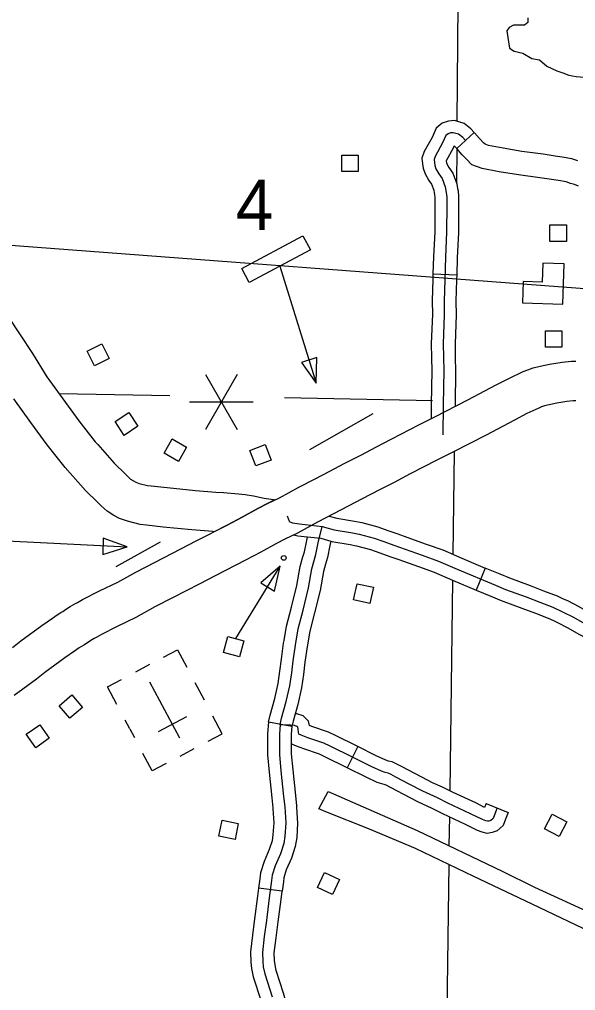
# Model space of a CAD drawing. Extents: x 61396 to 64680, y 55472 to 57605.
# Drawn here: x 62199.2 to 62308.8, y 55932.3 to 56123.6 of the extents above; entities that cross this region are included whole.
import ezdxf

# ---------------------------------------------------------------- set-up
doc = ezdxf.new("R2010")
doc.units = 0
for name, color, linetype in [('10', 7, 'Continuous'), ('15', 7, 'Continuous'), ('31', 7, 'Continuous'), ('35', 7, 'Continuous'), ('45', 7, 'Continuous'), ('46', 7, 'Continuous'), ('48', 7, 'Continuous'), ('5', 7, 'Continuous'), ('56', 7, 'Continuous'), ('57', 7, 'Continuous'), ('58', 7, 'Continuous'), ('Default', 7, 'Continuous')]:
    doc.layers.add(name, color=color, linetype=linetype)

msp = doc.modelspace()

# ---------------------------------------------------------------- linework, layer by layer
at = {"layer": '10'}
for points in [[(62196.72, 56065.34), (62199.33, 56061.45), (62201.71, 56057.78), (62204.53, 56053.2), (62207.71, 56048.84), (62210.88, 56044.54), (62214.1, 56040.41), (62214.6, 56039.85)], [(62208.17, 56035.32), (62204.65, 56039.83), (62201.41, 56044.23), (62198.04, 56048.84)], [(62214.6, 56039.85), (62217.84, 56036.2), (62220.08, 56034.03), (62220.64, 56033.43), (62221.08, 56033.05), (62221.65, 56032.71), (62222.14, 56032.45), (62222.75, 56032.22), (62224.43, 56031.81), (62225.14, 56031.71), (62228.3, 56031.37), (62233.85, 56030.81), (62237.85, 56030.51), (62239.42, 56030.4), (62242.35, 56030.13), (62243.68, 56030.04), (62245.33, 56029.75), (62247.41, 56029.31), (62249.24, 56029.02), (62249.49, 56028.94), (62248.07, 56028.25), (62246.16, 56027.25), (62243.04, 56025.55), (62240.12, 56024), (62237.55, 56022.7)], [(62237.55, 56022.7), (62237.28, 56022.72), (62233.16, 56023.03), (62227.48, 56023.6), (62224.19, 56023.96), (62222.97, 56024.13), (62220.45, 56024.74), (62218.92, 56025.32), (62217.8, 56025.91), (62216.47, 56026.71), (62215.25, 56027.77), (62214.53, 56028.52), (62212.19, 56030.81), (62208.17, 56035.32)]]:
    msp.add_lwpolyline(points, dxfattribs=at)
at = {"layer": '15'}
for points in [[(62248.07, 56028.25), (62250.4, 56029.38), (62254.26, 56031.47), (62257.47, 56033.12), (62260.37, 56034.65), (62263.15, 56036.1), (62266.58, 56037.86), (62269.45, 56039.33), (62272.59, 56041), (62277.89, 56043.72), (62281.08, 56045.34), (62287.56, 56048.66), (62293.15, 56051.62), (62295.76, 56052.96), (62298.46, 56054.23), (62299.37, 56054.59), (62300.45, 56054.97), (62301.84, 56055.32), (62303.68, 56055.72), (62306.15, 56056.11), (62308.01, 56056.27), (62308.83, 56056.27)], [(62308.89, 56048.45), (62308.33, 56048.45), (62307.09, 56048.35), (62305.13, 56048.04), (62303.62, 56047.71), (62302.69, 56047.48), (62302.11, 56047.27), (62301.58, 56047.06), (62299.22, 56045.95), (62296.77, 56044.69), (62291.16, 56041.72), (62284.63, 56038.39), (62281.46, 56036.76), (62276.2, 56034.07), (62273.06, 56032.4), (62270.15, 56030.91), (62266.75, 56029.17), (62264, 56027.73), (62261.08, 56026.19), (62257.9, 56024.56), (62253.96, 56022.42), (62251.47, 56021.22)], [(62197.8, 55999.9), (62199.45, 56001.18), (62203.59, 56004.23), (62205.66, 56005.66), (62206.11, 56005.96), (62206.59, 56006.29), (62207.31, 56006.75), (62207.72, 56006.99), (62208.27, 56007.36), (62209.17, 56007.94), (62210.11, 56008.48), (62210.6, 56008.74), (62211.59, 56009.32), (62214.94, 56011.05), (62218.56, 56012.76), (62222.14, 56014.75), (62225.9, 56016.7), (62230.98, 56019.32), (62234.15, 56020.97), (62240.12, 56024), (62243.04, 56025.55), (62246.16, 56027.25), (62248.07, 56028.25)], [(62251.47, 56021.22), (62249.84, 56020.36), (62246.74, 56018.67), (62243.72, 56017.07), (62237.72, 56014.02), (62234.58, 56012.38), (62229.49, 56009.76), (62225.83, 56007.86), (62222.13, 56005.81), (62218.41, 56004.04), (62215.35, 56002.47), (62214.44, 56001.94), (62213.92, 56001.65), (62213.23, 56001.26), (62212.55, 56000.82), (62211.85, 56000.35), (62211.37, 56000.08), (62210.94, 55999.8), (62210.48, 55999.48), (62210.01, 55999.18), (62208.13, 55997.87), (62204.16, 55994.94), (62202.51, 55993.66), (62198.13, 55990.45)]]:
    msp.add_lwpolyline(points, dxfattribs=at)
at = {"layer": '31'}
for p, q in [((62291, 56015.53), (62289.2, 56011.2)), ((62304.46, 56005.17), (62304.46, 56005.17)), ((62252.86, 55984.31), (62248.25, 55985.18)), ((62250.95, 55951.85), (62246.31, 55952.49))]:
    msp.add_line(p, q, dxfattribs=at)
for points in [[(62251.97, 56025.8), (62252.34, 56024.8), (62252.5, 56024.65), (62252.99, 56024.46), (62254.37, 56024.23), (62258.86, 56023.71)], [(62260.25, 56025.76), (62261.75, 56025.35), (62265.22, 56024.77), (62266.65, 56024.49), (62269.79, 56023.66), (62271.79, 56022.95), (62273.74, 56022.25), (62275.53, 56021.61)], [(62250.54, 55984.66), (62250.83, 55985.94), (62251.78, 55989.23), (62252.48, 55992.34), (62252.86, 55994.88), (62253.14, 55997.28), (62253.56, 56000.34), (62254.13, 56003.58), (62255.07, 56007.25), (62256.15, 56011.63), (62256.81, 56015.35), (62257.61, 56018.17), (62258.08, 56020.47), (62258.86, 56023.71)], [(62258.86, 56023.71), (62261.24, 56023.06), (62264.8, 56022.46), (62266.13, 56022.2), (62269.1, 56021.42), (62271, 56020.74), (62272.95, 56020.04), (62278.59, 56018.04), (62281.77, 56016.92), (62285.44, 56015.31), (62293.01, 56012.16), (62295.01, 56011.33), (62299.07, 56009.84), (62301.73, 56008.8), (62304.33, 56007.81), (62306.25, 56006.93), (62308.41, 56005.84), (62310.55, 56004.59)], [(62253.19, 56022.05), (62254.04, 56021.91), (62255.96, 56021.69)], [(62255, 56017.56), (62255.33, 56018.72), (62255.79, 56020.98), (62255.96, 56021.69)], [(62255.96, 56021.69), (62258.6, 56021.39), (62260.57, 56020.81)], [(62260.57, 56020.81), (62260.37, 56019.97), (62259.89, 56017.61), (62259.51, 56016.28)], [(62260.57, 56020.81), (62260.73, 56020.77), (62264.38, 56020.15), (62265.61, 56019.92), (62268.4, 56019.18), (62270.21, 56018.54), (62272.16, 56017.83), (62273.96, 56017.19)], [(62275.53, 56021.61), (62279.38, 56020.25), (62282.63, 56019.1), (62286.36, 56017.46), (62291, 56015.53)], [(62251.34, 56001.23), (62251.83, 56004.08), (62252.8, 56007.83), (62253.86, 56012.12), (62254.52, 56015.87), (62255, 56017.56)], [(62273.96, 56017.19), (62277.81, 56015.83), (62280.91, 56014.74), (62284.52, 56013.15), (62289.2, 56011.2)], [(62259.51, 56016.28), (62259.1, 56014.82), (62258.45, 56011.14), (62257.34, 56006.68), (62256.42, 56003.09), (62255.96, 56000.43)], [(62306.42, 56009.43), (62305.23, 56009.98), (62302.57, 56010.99), (62299.9, 56012.03), (62295.87, 56013.51), (62293.91, 56014.32), (62291, 56015.53)], [(62289.2, 56011.2), (62292.11, 56009.99), (62294.16, 56009.14), (62298.24, 56007.65), (62300.88, 56006.62), (62303.42, 56005.65), (62304.46, 56005.17)], [(62321.17, 56002.34), (62319.35, 56003.07), (62313.72, 56005.61), (62311.67, 56006.65), (62309.54, 56007.89), (62307.27, 56009.04), (62306.42, 56009.43)], [(62304.46, 56005.17), (62305.24, 56004.82), (62307.29, 56003.78), (62309.43, 56002.53), (62311.7, 56001.38), (62317.51, 55998.76), (62319.42, 55997.99)], [(62248.25, 55985.18), (62248.56, 55986.53), (62249.5, 55989.82), (62250.18, 55992.77), (62250.53, 55995.19), (62250.82, 55997.58), (62251.25, 56000.7), (62251.34, 56001.23)], [(62255.96, 56000.43), (62255.88, 55999.98), (62255.46, 55996.98), (62255.18, 55994.57), (62254.79, 55991.91), (62254.05, 55988.65), (62253.1, 55985.35), (62252.86, 55984.31)], [(62250.54, 55984.66), (62250.42, 55982.87), (62250.42, 55978.81), (62250.7, 55975.56), (62251.23, 55970.5), (62251.46, 55968.46), (62251.65, 55965.3), (62251.48, 55962.72), (62251.26, 55961.24), (62250.62, 55959.22), (62249.58, 55956.87), (62248.99, 55955), (62248.88, 55953.99), (62248.41, 55950.55), (62247.85, 55946.1), (62247.43, 55942.94), (62247.06, 55939.81), (62247.12, 55938.04), (62247.23, 55936.98), (62247.51, 55935.61), (62248.99, 55931.05)], [(62248.25, 55985.18), (62248.08, 55982.94), (62248.08, 55978.71), (62248.37, 55975.34), (62248.9, 55970.25), (62249.12, 55968.26), (62249.13, 55968.07)], [(62252.86, 55984.31), (62252.76, 55982.79), (62252.76, 55978.91), (62253.03, 55975.79), (62253.56, 55970.75), (62253.79, 55968.66), (62253.81, 55968.36)], [(62249.13, 55968.07), (62249.3, 55965.3), (62249.15, 55962.97), (62248.97, 55961.77), (62248.42, 55960.06), (62247.38, 55957.7), (62246.69, 55955.48), (62246.56, 55954.28), (62246.31, 55952.49)], [(62253.81, 55968.36), (62254, 55965.29), (62253.82, 55962.47), (62253.55, 55960.7), (62252.81, 55958.39), (62251.78, 55956.05), (62251.3, 55954.51), (62251.21, 55953.7), (62250.95, 55951.85)], [(62246.31, 55952.49), (62246.08, 55950.86), (62245.52, 55946.4), (62245.1, 55943.23), (62244.71, 55939.91), (62244.78, 55937.88), (62244.91, 55936.62), (62245.17, 55935.33)], [(62249.77, 55936.27), (62249.55, 55937.34), (62249.46, 55938.2), (62249.41, 55939.71), (62249.75, 55942.65), (62250.17, 55945.8), (62250.73, 55950.24), (62250.95, 55951.85)], [(62254.37, 55920.6), (62252.98, 55925.64), (62251.24, 55931.74), (62249.78, 55936.21), (62249.77, 55936.27)], [(62245.17, 55935.33), (62245.24, 55935.01), (62246.75, 55930.36), (62248.47, 55924.37), (62249.85, 55919.35)]]:
    msp.add_lwpolyline(points, dxfattribs=at)
at = {"layer": '35'}
msp.add_lwpolyline([(62299.41, 56123.93), (62299.41, 56123.04), (62298.76, 56122.51), (62297.74, 56122.47), (62296.6, 56122.47), (62295.71, 56122.06), (62295.26, 56121.37), (62295.43, 56120.07), (62295.75, 56117.96), (62296.69, 56117.35), (62298.43, 56116.99), (62300.18, 56115.93), (62301.68, 56115.69), (62303.14, 56114.39), (62305.09, 56113.53), (62306.27, 56113.09), (62307.45, 56112.64), (62308.95, 56112.36), (62310.49, 56112.28), (62312.28, 56112.32), (62313.05, 56112.15)], dxfattribs=at)
at = {"layer": '45'}
for p, q in [((62288.83, 56101.34), (62285.37, 56098.18)), ((62280.69, 56073.47), (62285.38, 56073.32)), ((62265.86, 55980.36), (62263.77, 55976.16)), ((62291.2, 55969.16), (62295.53, 55967.37))]:
    msp.add_line(p, q, dxfattribs=at)
for points in [[(62288.83, 56101.34), (62288.15, 56102.09), (62286.83, 56103.13), (62284.95, 56103.68), (62283.73, 56103.6), (62282.51, 56103.19), (62281.32, 56102.19), (62280.5, 56100.38), (62278.96, 56097.6), (62278.52, 56096.3), (62278.65, 56095.17), (62278.75, 56094.34), (62279.14, 56093.22), (62279.87, 56091.92), (62280.4, 56091.17), (62280.83, 56090), (62280.93, 56089.46)], [(62287.1, 56099.76), (62286.55, 56100.37), (62285.74, 56101.01), (62284.69, 56101.31), (62284.18, 56101.28), (62283.68, 56101.11), (62283.24, 56100.74), (62282.6, 56099.32), (62281.11, 56096.65), (62280.91, 56096.05), (62280.98, 56095.44), (62281.04, 56094.87), (62281.28, 56094.19), (62281.85, 56093.18), (62282.5, 56092.27), (62283.1, 56090.61), (62283.31, 56089.5), (62283.41, 56088.62), (62283.41, 56087.04), (62283.37, 56081.74), (62283.14, 56076.78), (62283, 56072.39), (62282.87, 56068.14), (62282.93, 56065.44), (62282.7, 56059.73), (62282.8, 56054.47), (62282.7, 56047.72), (62282.66, 56041.77)], [(62285.37, 56098.18), (62284.94, 56098.65), (62284.89, 56098.69), (62284.69, 56098.27), (62283.3, 56095.76), (62283.31, 56095.71), (62283.34, 56095.4), (62283.42, 56095.16), (62283.84, 56094.43), (62284.59, 56093.36), (62285.37, 56091.23), (62285.54, 56090.3)], [(62280.93, 56089.46), (62280.99, 56089.16), (62281.06, 56088.49), (62281.06, 56087.04), (62281.03, 56081.8), (62280.79, 56076.87), (62280.69, 56073.47)], [(62285.54, 56090.3), (62285.63, 56089.84), (62285.75, 56088.76), (62285.75, 56087.03), (62285.72, 56081.67), (62285.48, 56076.68), (62285.38, 56073.32)], [(62280.69, 56073.47), (62280.66, 56072.46), (62280.52, 56068.15), (62280.59, 56065.46), (62280.35, 56059.76), (62280.41, 56056.86)], [(62285.38, 56073.32), (62285.34, 56072.32), (62285.21, 56068.13), (62285.28, 56065.42), (62285.04, 56059.71), (62285.1, 56056.95)], [(62280.41, 56056.86), (62280.46, 56054.46), (62280.35, 56047.74), (62280.34, 56044.97)], [(62285.1, 56056.95), (62285.14, 56054.47), (62285.04, 56047.69), (62285.04, 56047.37)], [(62265.86, 55980.36), (62265.85, 55980.36), (62261.45, 55982.54), (62260.08, 55983.21), (62256.82, 55984.31), (62256.37, 55984.48), (62256.18, 55985.35), (62255.1, 55986.43), (62253.88, 55986.78), (62253.53, 55986.83)], [(62293.36, 55968.26), (62292.81, 55966.92), (62292.53, 55966.18), (62292.12, 55965.81), (62291.72, 55965.67), (62291.47, 55965.63), (62291.1, 55965.72), (62290.43, 55965.97), (62288.12, 55967.13), (62283.64, 55969.21), (62281.56, 55970.25), (62278.71, 55971.54), (62276.01, 55972.97), (62273.38, 55974.36), (62272.45, 55974.85), (62271.85, 55975.1), (62271.25, 55975.26), (62270.56, 55975.49), (62268.5, 55976.42), (62264.8, 55978.27), (62260.41, 55980.44), (62259.19, 55981.04), (62256.02, 55982.1), (62254.71, 55982.61), (62254.25, 55982.82), (62254.15, 55983.21), (62254.11, 55983.86), (62254.04, 55984.18), (62253.88, 55984.34), (62253.39, 55984.48), (62252.58, 55984.6), (62250.54, 55984.66)], [(62263.77, 55976.16), (62263.76, 55976.17), (62259.38, 55978.33), (62258.3, 55978.87), (62255.23, 55979.9), (62253.8, 55980.45), (62252.76, 55980.91)], [(62280.63, 55973.24), (62279.75, 55973.65), (62277.11, 55975.05), (62274.47, 55976.44), (62273.46, 55976.97), (62272.62, 55977.32), (62271.93, 55977.51), (62271.41, 55977.68), (62269.51, 55978.54), (62265.86, 55980.36)], [(62278.69, 55968.98), (62277.68, 55969.44), (62274.92, 55970.9), (62272.29, 55972.29), (62271.45, 55972.73), (62271.09, 55972.88), (62270.58, 55973.02), (62269.71, 55973.31), (62267.5, 55974.3), (62263.77, 55976.16)], [(62291.2, 55969.16), (62290.87, 55968.37), (62289.14, 55969.24), (62284.65, 55971.32), (62282.57, 55972.36), (62280.63, 55973.24)], [(62295.53, 55967.37), (62294.99, 55966.06), (62294.52, 55964.82), (62293.33, 55963.76), (62292.33, 55963.4), (62291.39, 55963.23), (62290.4, 55963.48), (62289.49, 55963.83), (62287.1, 55965.02), (62282.62, 55967.1), (62280.55, 55968.13), (62278.69, 55968.98)]]:
    msp.add_lwpolyline(points, dxfattribs=at)
at = {"layer": '46'}
for points in [[(62309.25, 56095.78), (62308.1, 56096.16), (62306.19, 56096.48), (62304.79, 56096.69), (62302.42, 56097.08), (62298.24, 56097.62), (62294.54, 56098.24), (62291.63, 56098.79), (62290.96, 56099.02), (62290.66, 56099.33), (62289.88, 56100.14), (62288.86, 56101.3)], [(62309.36, 56090.75), (62308.58, 56091.08), (62307.83, 56091.31), (62306.96, 56091.6), (62305.44, 56091.86), (62304.07, 56092.06), (62301.75, 56092.44), (62297.55, 56092.98), (62293.71, 56093.62), (62290.42, 56094.24), (62288.36, 56094.96), (62287.28, 56096.09), (62286.43, 56096.97), (62285.38, 56098.19)]]:
    msp.add_lwpolyline(points, dxfattribs=at)
at = {"layer": '48'}
for p, q in [((62242.1, 56053.68), (62235.85, 56042.86)), ((62235.85, 56053.68), (62242.1, 56042.86)), ((62232.72, 56048.27), (62245.22, 56048.27))]:
    msp.add_line(p, q, dxfattribs=at)
at = {"layer": '5'}
for points in [[(62285.89, 56165.37), (62285.42, 56103.54)], [(62285.38, 56098.19), (62285.33, 56091.35)], [(62228.83, 56049.45), (62206.98, 56049.85)], [(62280.57, 56048.51), (62251.39, 56049.04)], [(62284.87, 56038.4), (62284.61, 56018.23)], [(62284.54, 56013.14), (62283.99, 55971.63)], [(62283.92, 55966.49), (62283.85, 55960.82)], [(62283.8, 55957.14), (62282.84, 55884.38)]]:
    msp.add_lwpolyline(points, dxfattribs=at)
at = {"layer": '56'}
for points in [[(62262.7, 56093.64), (62262.7, 56096.89), (62265.96, 56096.89), (62265.96, 56093.64)], [(62303.74, 56079.89), (62303.74, 56083.14), (62307, 56083.14), (62307, 56079.89)], [(62244.47, 56071.77), (62242.99, 56074.52), (62255.04, 56080.98), (62256.52, 56078.23)], [(62302.85, 56059.02), (62302.85, 56062.27), (62306.11, 56062.27), (62306.11, 56059.02)], [(62213.96, 56055.35), (62212.5, 56058.26), (62215.42, 56059.71), (62216.88, 56056.81)], [(62257.78, 56057), (62254.74, 56056.05), (62257.69, 56051.96)], [(62219.78, 56041.68), (62218.02, 56044.41), (62220.75, 56046.19), (62222.52, 56043.46)], [(62227.69, 56038.14), (62229.28, 56040.97), (62232.12, 56039.37), (62230.53, 56036.54)], [(62245.74, 56035.64), (62244.57, 56038.67), (62247.61, 56039.85), (62248.78, 56036.82)], [(62246.73, 56012.65), (62249.44, 56010.98), (62250.59, 56015.89)], [(62265.05, 56009.28), (62265.76, 56012.45), (62268.94, 56011.74), (62268.23, 56008.57)], [(62239.4, 55998.91), (62240.24, 56002.05), (62243.39, 56001.21), (62242.55, 55998.07)], [(62209.12, 55985.93), (62206.99, 55988.39), (62209.46, 55990.52), (62211.59, 55988.06)], [(62202.38, 55980.13), (62200.51, 55982.8), (62203.18, 55984.67), (62205.05, 55982.01)], [(62305.55, 55962.63), (62302.68, 55964.15), (62304.21, 55967.03), (62307.08, 55965.51)], [(62238.47, 55962.68), (62239.11, 55965.87), (62242.31, 55965.23), (62241.67, 55962.04)], [(62257.94, 55952.61), (62259.31, 55955.56), (62262.27, 55954.18), (62260.9, 55951.24)]]:
    msp.add_lwpolyline(points, close=True, dxfattribs=at)
for points in [[(62250.49, 56075), (62257.69, 56051.96)], [(62256.39, 56038.9), (62268.92, 56045.97)], [(62241.81, 56001.63), (62250.59, 56015.89)]]:
    msp.add_lwpolyline(points, dxfattribs=at)
msp.add_circle((62251.27, 56017.53), 0.469, dxfattribs=at)
at = {"layer": '57'}
for p, q in [((62224.79, 55996.5), (62222.03, 55995.03)), ((62230.78, 55981.99), (62224.9, 55993.02)), ((62235.64, 55989.48), (62233.8, 55992.92)), ((62232.07, 55986.21), (62226.53, 55983.26)), ((62227.84, 55987.5), (62227.84, 55987.5)), ((62227.84, 55987.5), (62227.84, 55987.5)), ((62220.95, 55983.82), (62220.01, 55985.57)), ((62220.95, 55983.82), (62221.85, 55982.13)), ((62230.86, 55978.49), (62233.61, 55979.96)), ((62258.21, 55968.12), (62260.03, 55971.5)), ((62260.03, 55971.5), (62277.55, 55963.81)), ((62259.54, 55967.48), (62258.21, 55968.12)), ((62268.15, 55964.11), (62259.54, 55967.48)), ((62277.25, 55960.29), (62268.15, 55964.11)), ((62277.55, 55963.81), (62294.34, 55955.84)), ((62288.76, 55954.76), (62277.25, 55960.29)), ((62294.34, 55955.84), (62300.7, 55952.65)), ((62300.26, 55949.28), (62288.76, 55954.76)), ((62300.7, 55952.65), (62316.12, 55945.56)), ((62315.92, 55941.84), (62300.26, 55949.28))]:
    msp.add_line(p, q, dxfattribs=at)
for points in [[(62227.56, 55997.98), (62230.32, 55999.45), (62232.16, 55996)], [(62218.37, 55988.65), (62216.53, 55992.1), (62219.29, 55993.57)], [(62236.39, 55981.43), (62239.14, 55982.9), (62237.31, 55986.35)], [(62228.12, 55977.02), (62225.36, 55975.55), (62223.52, 55979)]]:
    msp.add_lwpolyline(points, dxfattribs=at)
at = {"layer": '58'}
for points in [[(62306.27, 56067.54), (62306.54, 56075.47), (62302.35, 56075.61), (62302.22, 56071.86), (62298.47, 56071.99), (62298.33, 56067.81)], [(62215.69, 56021.42), (62215.6, 56018.23), (62220.43, 56019.7)]]:
    msp.add_lwpolyline(points, close=True, dxfattribs=at)
for points in [[(62169.02, 56013.7), (62179.52, 56021.75), (62220.43, 56019.7)], [(62218.26, 56015.86), (62226.99, 56020.73)]]:
    msp.add_lwpolyline(points, dxfattribs=at)
at = {"layer": 'Default'}
msp.add_line((62028.43, 56091.83), (62651.44, 56045.01), dxfattribs=at)

# ---------------------------------------------------------------- texts
at = {"layer": '56'}
msp.add_text('4', height=9.9, dxfattribs=at).set_placement((62241.83, 56082.15))

doc.saveas('drawing.dxf')
